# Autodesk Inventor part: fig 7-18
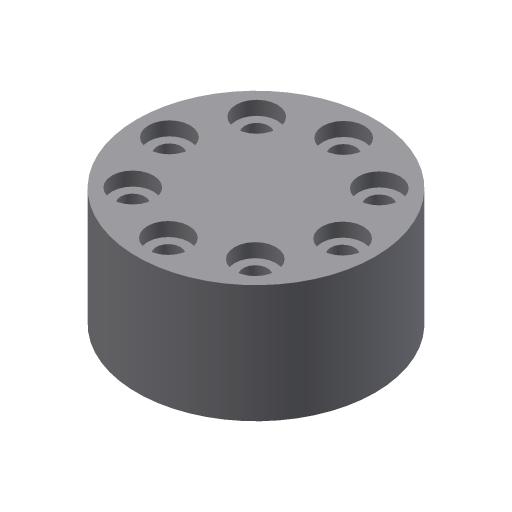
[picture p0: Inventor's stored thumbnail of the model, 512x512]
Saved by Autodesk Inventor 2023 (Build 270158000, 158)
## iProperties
Created: 2004-05
Part Number: fig 7-18
Document SubType Name: Modeling
Designer: CADCIM Technologies
Manufacturer: Standard
Standards Organization: Custom
Density: 1 g/cm^3
Material: Generic
Appearance: Default
Author: CADCIM Technologies
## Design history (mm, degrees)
sketch "Sketch1"
  geometry: C1 r 17.175 at (0, 0)
  constraints: 1 centre point
extrude "Extrusion1" new body sketch "Sketch1" distance "d0" = 17; taper "d1" = 0 deg
sketch "Sketch2"
  geometry: 1 further point
hole "Hole1" sketch "Sketch2" at (12.571, -0.074) diameter "d2" = 3.5; stored, may be unused: countersink angle "d6" = 90 deg, drill point angle "d8" = 118 deg; dims "d3" = 6, "d4" = 6, "d5" = 2, "d7" = 8
pattern_circular "Circular Pattern1" dims angle "d11" = 360 deg
body "Solid1"
